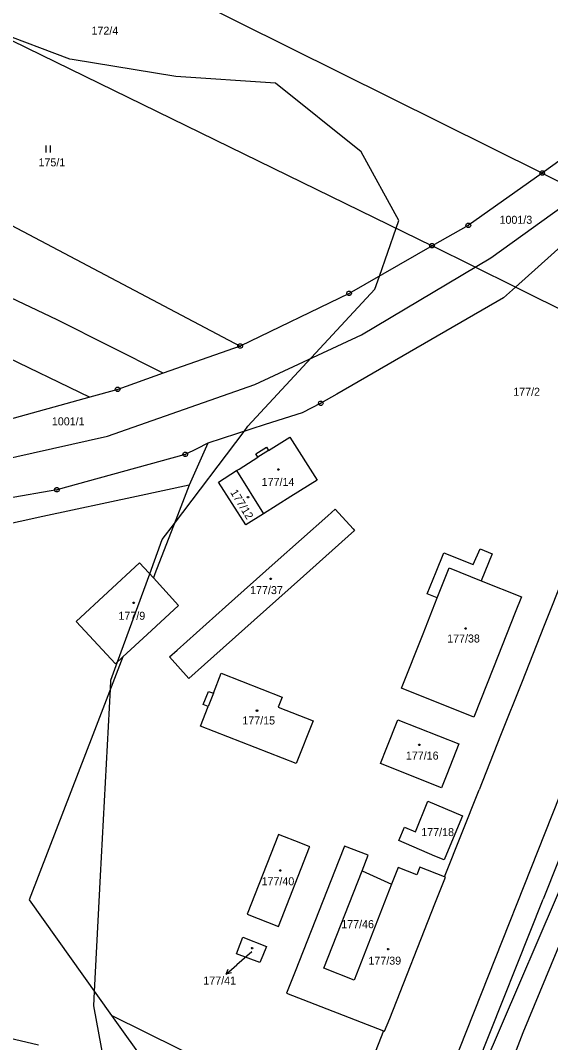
# Model space of a CAD drawing. Extents: x -755359 to -754474, y -1162585 to -1161655.
# Drawn here: x -755011 to -754898.3, y -1162361.4 to -1162144.3 of the extents above; entities that cross this region are included whole.
import ezdxf

# ---------------------------------------------------------------- set-up
doc = ezdxf.new("R2010")
doc.units = 0
for name, color, linetype in [('Vrstva 1', 7, 'Continuous'), ('Vrstva 11', 7, 'Continuous'), ('Vrstva 12', 7, 'Continuous'), ('Vrstva 2', 7, 'Continuous'), ('Vrstva 3', 7, 'Continuous'), ('Vrstva 4', 7, 'Continuous'), ('Vrstva 5', 7, 'Continuous'), ('Vrstva 6', 7, 'Continuous'), ('Vrstva 7', 7, 'Continuous'), ('Vrstva 8', 7, 'Continuous')]:
    doc.layers.add(name, color=color, linetype=linetype)

msp = doc.modelspace()

# ---------------------------------------------------------------- linework, layer by layer
at = {"layer": 'Vrstva 1'}
for p, q in [((-754900.06, -1162176.77), (-755075.64, -1162089.56)), ((-755078.18, -1162116.73), (-754923.5, -1162192.2)), ((-754896.07, -1162173.88), (-754900.06, -1162176.77)), ((-754900.06, -1162176.77), (-754915.78, -1162187.87)), ((-754900.06, -1162176.77), (-754886.23, -1162183.69)), ((-755003.14, -1162207.94), (-755054.32, -1162183.78)), ((-754888.26, -1162185.23), (-754905.78, -1162201)), ((-755012.93, -1162187.79), (-754964.26, -1162213.49)), ((-754915.78, -1162187.87), (-754923.5, -1162192.2)), ((-754923.5, -1162192.2), (-754941.12, -1162202.31)), ((-754905.78, -1162201), (-754923.5, -1162192.2)), ((-754905.78, -1162201), (-754908.27, -1162203.24)), ((-754876.85, -1162215.37), (-754905.78, -1162201)), ((-755040.35, -1162203.08), (-754996.22, -1162224.35)), ((-754941.12, -1162202.31), (-754964.26, -1162213.49)), ((-754908.27, -1162203.24), (-754943.74, -1162223.69)), ((-754980.63, -1162219.28), (-755003.14, -1162207.94)), ((-754964.26, -1162213.49), (-754980.63, -1162219.28)), ((-754980.63, -1162219.28), (-754990.29, -1162222.69)), ((-754990.29, -1162222.69), (-754996.22, -1162224.35)), ((-754996.22, -1162224.35), (-755014.83, -1162229.55)), ((-754943.74, -1162223.69), (-754947.14, -1162225.65)), ((-754947.14, -1162225.65), (-754951.07, -1162227.67)), ((-754951.07, -1162227.67), (-754958.95, -1162230.19)), ((-754958.95, -1162230.19), (-754971.15, -1162234.1)), ((-754958.23, -1162235.71), (-754953.68, -1162232.85)), ((-754953.68, -1162232.85), (-754947.93, -1162241.97)), ((-754973.51, -1162235.29), (-754975.93, -1162236.51)), ((-754972, -1162236.02), (-754975.1, -1162243.04)), ((-754971.15, -1162234.1), (-754973.51, -1162235.29)), ((-754971.15, -1162234.1), (-754972, -1162236.02)), ((-754960.95, -1162236.39), (-754958.69, -1162234.97)), ((-754958.69, -1162234.97), (-754958.23, -1162235.71)), ((-754975.93, -1162236.51), (-754994.22, -1162241.55)), ((-754964.51, -1162239.63), (-754960.48, -1162237.12)), ((-754960.48, -1162237.12), (-754960.95, -1162236.39)), ((-754968.85, -1162242.38), (-754965.02, -1162239.9)), ((-754965.02, -1162239.9), (-754964.51, -1162239.63)), ((-754965.02, -1162239.9), (-754959.28, -1162249.1)), ((-754994.22, -1162241.55), (-755003.23, -1162244.03)), ((-754963.09, -1162251.49), (-754968.85, -1162242.38)), ((-754947.93, -1162241.97), (-754953.52, -1162245.48)), ((-755003.23, -1162244.03), (-755013.79, -1162245.86)), ((-754975.1, -1162243.04), (-754986.3, -1162245.44)), ((-754975.1, -1162243.04), (-754977.59, -1162249.49)), ((-754986.3, -1162245.44), (-755006.22, -1162249.72)), ((-754953.52, -1162245.48), (-754959.28, -1162249.1)), ((-754959.28, -1162249.1), (-754963.09, -1162251.49)), ((-754945.64, -1162249.55), (-754944.05, -1162248.14)), ((-754944.05, -1162248.14), (-754940.25, -1162252.33)), ((-755006.22, -1162249.72), (-755027.5, -1162254.28)), ((-754977.59, -1162249.49), (-754982.38, -1162261.87)), ((-754956.8, -1162259.49), (-754945.64, -1162249.55)), ((-754950.82, -1162262.37), (-754939.94, -1162252.67)), ((-754940.25, -1162252.33), (-754939.94, -1162252.67)), ((-754922.63, -1162261.43), (-754921.01, -1162257.39)), ((-754921.01, -1162257.39), (-754914.72, -1162259.89)), ((-754914.72, -1162259.89), (-754913.29, -1162256.54)), ((-754913.29, -1162256.54), (-754910.69, -1162257.6)), ((-754910.69, -1162257.6), (-754913.05, -1162263.33)), ((-754985.67, -1162259.55), (-754999.09, -1162271.99)), ((-754985.67, -1162259.55), (-754982.72, -1162262.75)), ((-754967.36, -1162268.89), (-754956.8, -1162259.49)), ((-754982.38, -1162261.87), (-754982.72, -1162262.75)), ((-754924.5, -1162266.11), (-754922.63, -1162261.43)), ((-754895.21, -1162261.65), (-754899.8, -1162273.21)), ((-754982.72, -1162262.75), (-754977.34, -1162268.59)), ((-754961.31, -1162271.72), (-754950.82, -1162262.37)), ((-754913.05, -1162263.33), (-754904.47, -1162266.73)), ((-754922.38, -1162266.96), (-754924.5, -1162266.11)), ((-754977.34, -1162268.59), (-754984.03, -1162274.74)), ((-754930.02, -1162407.36), (-754870.17, -1162267.96)), ((-754925.41, -1162274.6), (-754922.38, -1162266.96)), ((-754904.47, -1162266.73), (-754905.81, -1162270.11)), ((-754977.67, -1162278.08), (-754967.36, -1162268.89)), ((-754905.81, -1162270.11), (-754910.45, -1162281.8)), ((-754990.78, -1162280.96), (-754999.09, -1162271.99)), ((-754971.86, -1162281.13), (-754961.31, -1162271.72)), ((-754989.19, -1162279.49), (-754984.03, -1162274.74)), ((-754930, -1162286.19), (-754925.41, -1162274.6)), ((-754899.8, -1162273.21), (-754904.37, -1162284.73)), ((-754989.19, -1162279.49), (-754995.6, -1162296.07)), ((-754989.19, -1162279.49), (-754990.78, -1162280.96)), ((-754979.27, -1162279.5), (-754977.67, -1162278.08)), ((-754979.27, -1162279.5), (-754975.18, -1162284.09)), ((-754975.18, -1162284.09), (-754971.86, -1162281.13)), ((-754969.96, -1162287.23), (-754968.29, -1162283)), ((-754968.29, -1162283), (-754955.36, -1162288.07)), ((-754910.45, -1162281.8), (-754914.62, -1162292.29)), ((-754904.37, -1162284.73), (-754908.92, -1162296.21)), ((-754972.13, -1162289.65), (-754971, -1162286.83)), ((-754971, -1162286.83), (-754969.96, -1162287.23)), ((-754955.36, -1162288.07), (-754956.18, -1162290.17)), ((-754914.62, -1162292.29), (-754930, -1162286.19)), ((-754972.72, -1162294.22), (-754971.08, -1162290.06)), ((-754971.08, -1162290.06), (-754972.13, -1162289.65)), ((-754956.18, -1162290.17), (-754948.75, -1162293.08)), ((-754952.39, -1162302.17), (-754972.72, -1162294.22)), ((-754948.75, -1162293.08), (-754952.39, -1162302.17)), ((-754933.11, -1162298.79), (-754930.78, -1162292.9)), ((-754930.78, -1162292.9), (-754917.8, -1162298.01)), ((-754995.6, -1162296.07), (-755004.94, -1162320.25)), ((-754908.92, -1162296.21), (-754913.49, -1162307.74)), ((-754934.43, -1162302.13), (-754933.11, -1162298.79)), ((-754917.8, -1162298.01), (-754920.35, -1162304.49)), ((-754921.45, -1162307.29), (-754934.43, -1162302.13)), ((-754920.35, -1162304.49), (-754921.45, -1162307.29)), ((-754920.81, -1162326.21), (-754913.49, -1162307.74)), ((-754927.01, -1162316.65), (-754924.39, -1162310.17)), ((-754924.39, -1162310.17), (-754917, -1162313.28)), ((-754917, -1162313.28), (-754919.73, -1162319.74)), ((-754930.54, -1162318.52), (-754929.32, -1162315.68)), ((-754929.32, -1162315.68), (-754927.01, -1162316.65)), ((-754956.15, -1162317.23), (-754962.81, -1162334.17)), ((-754951.35, -1162319.11), (-754956.15, -1162317.23)), ((-754922.89, -1162321.82), (-754930.54, -1162318.52)), ((-755004.94, -1162320.25), (-755009.14, -1162331.11)), ((-754956.1, -1162336.8), (-754949.5, -1162319.95)), ((-754949.46, -1162319.85), (-754951.35, -1162319.11)), ((-754949.5, -1162319.95), (-754949.46, -1162319.85)), ((-754942.11, -1162319.68), (-754943.32, -1162322.74)), ((-754937.04, -1162321.65), (-754942.11, -1162319.68)), ((-754919.73, -1162319.74), (-754920.94, -1162322.61)), ((-754887.61, -1162319.28), (-754904.19, -1162359.38)), ((-754943.32, -1162322.74), (-754952.59, -1162346.32)), ((-754938.35, -1162324.98), (-754937.04, -1162321.65)), ((-754920.94, -1162322.61), (-754922.89, -1162321.82)), ((-754946.47, -1162345.65), (-754938.35, -1162324.98)), ((-754938.35, -1162324.98), (-754932.08, -1162327.81)), ((-754930.68, -1162324.22), (-754932.08, -1162327.81)), ((-754926.7, -1162325.77), (-754930.68, -1162324.22)), ((-754926.07, -1162324.16), (-754926.7, -1162325.77)), ((-754920.81, -1162326.21), (-754926.07, -1162324.16)), ((-754922.89, -1162331.96), (-754920.65, -1162326.27)), ((-754920.65, -1162326.27), (-754920.81, -1162326.21)), ((-754932.08, -1162327.81), (-754940.04, -1162348.18)), ((-755009.14, -1162331.11), (-754991.59, -1162355.66)), ((-754932.49, -1162356.33), (-754922.89, -1162331.96)), ((-754962.81, -1162334.17), (-754956.1, -1162336.8)), ((-754964.25, -1162340.51), (-754963.68, -1162339.01)), ((-754963.68, -1162339.01), (-754958.7, -1162341)), ((-755096.49, -1162341), (-755007.12, -1162361.91)), ((-754965.03, -1162342.55), (-754964.25, -1162340.51)), ((-754960.08, -1162344.45), (-754965.03, -1162342.55)), ((-754958.7, -1162341), (-754959.46, -1162342.9)), ((-754959.46, -1162342.9), (-754960.08, -1162344.45)), ((-754952.59, -1162346.32), (-754954.4, -1162350.9)), ((-754940.04, -1162348.18), (-754946.47, -1162345.65)), ((-754954.4, -1162350.9), (-754933.79, -1162358.94)), ((-754942.18, -1162380.1), (-754991.59, -1162355.66)), ((-754991.59, -1162355.66), (-754983.11, -1162367.53)), ((-754933.56, -1162359.03), (-754932.49, -1162356.33)), ((-754933.79, -1162358.94), (-754942.18, -1162380.1)), ((-754933.79, -1162358.94), (-754933.56, -1162359.03)), ((-754904.19, -1162359.38), (-754920.39, -1162401.05))]:
    msp.add_line(p, q, dxfattribs=at)
at = {"layer": 'Vrstva 11'}
for p, q in [((-755000.49, -1162152.59), (-755019.15, -1162145.53)), ((-755000, -1162152.67), (-755000.49, -1162152.59)), ((-754977.91, -1162156.23), (-755000, -1162152.67)), ((-754956.78, -1162157.69), (-754977.91, -1162156.23)), ((-754938.57, -1162172.26), (-754956.78, -1162157.69)), ((-754930.56, -1162186.83), (-754938.57, -1162172.26)), ((-754931.13, -1162188.48), (-754930.56, -1162186.83)), ((-754934.68, -1162198.62), (-754931.13, -1162188.48)), ((-754935.66, -1162201.4), (-754934.68, -1162198.62)), ((-754962.61, -1162230.54), (-754935.66, -1162201.4)), ((-754978.24, -1162251.17), (-754963.43, -1162231.63)), ((-754963.43, -1162231.63), (-754962.61, -1162230.54)), ((-754980.82, -1162254.58), (-754978.24, -1162251.17)), ((-754983.5, -1162261.9), (-754980.82, -1162254.58)), ((-754990.32, -1162280.53), (-754983.5, -1162261.9)), ((-754991.75, -1162284.45), (-754990.32, -1162280.53)), ((-754991.85, -1162286.38), (-754991.75, -1162284.45)), ((-754993.94, -1162325.98), (-754991.85, -1162286.38)), ((-754887.61, -1162319.28), (-754904.19, -1162359.38)), ((-754995.23, -1162350.57), (-754993.94, -1162325.98)), ((-754995.39, -1162353.66), (-754995.23, -1162350.57)), ((-754993.26, -1162365.15), (-754995.39, -1162353.66)), ((-754904.19, -1162359.38), (-754920.39, -1162401.05))]:
    msp.add_line(p, q, dxfattribs=at)
at = {"layer": 'Vrstva 12'}
for p, q in [((-754958.23, -1162235.71), (-754953.68, -1162232.85)), ((-754953.68, -1162232.85), (-754947.93, -1162241.97)), ((-754958.23, -1162235.71), (-754960.48, -1162237.12)), ((-754964.51, -1162239.63), (-754960.48, -1162237.12)), ((-754968.85, -1162242.38), (-754965.02, -1162239.9)), ((-754965.02, -1162239.9), (-754964.51, -1162239.63)), ((-754965.02, -1162239.9), (-754959.28, -1162249.1)), ((-754965.02, -1162239.9), (-754959.28, -1162249.1)), ((-754963.09, -1162251.49), (-754968.85, -1162242.38)), ((-754947.93, -1162241.97), (-754953.52, -1162245.48)), ((-754953.52, -1162245.48), (-754959.28, -1162249.1)), ((-754959.28, -1162249.1), (-754963.09, -1162251.49)), ((-754945.64, -1162249.55), (-754944.05, -1162248.14)), ((-754944.05, -1162248.14), (-754940.25, -1162252.33)), ((-754956.8, -1162259.49), (-754945.64, -1162249.55)), ((-754950.82, -1162262.37), (-754939.94, -1162252.67)), ((-754940.25, -1162252.33), (-754939.94, -1162252.67)), ((-754985.67, -1162259.55), (-754999.09, -1162271.99)), ((-754985.67, -1162259.55), (-754982.72, -1162262.75)), ((-754967.36, -1162268.89), (-754956.8, -1162259.49)), ((-754922.38, -1162266.96), (-754919.87, -1162260.62)), ((-754919.87, -1162260.62), (-754913.05, -1162263.33)), ((-754982.72, -1162262.75), (-754977.34, -1162268.59)), ((-754961.31, -1162271.72), (-754950.82, -1162262.37)), ((-754913.05, -1162263.33), (-754904.47, -1162266.73)), ((-754977.34, -1162268.59), (-754984.03, -1162274.74)), ((-754925.41, -1162274.6), (-754922.38, -1162266.96)), ((-754904.47, -1162266.73), (-754905.81, -1162270.11)), ((-754977.67, -1162278.08), (-754967.36, -1162268.89)), ((-754905.81, -1162270.11), (-754910.45, -1162281.8)), ((-754990.78, -1162280.96), (-754999.09, -1162271.99)), ((-754971.86, -1162281.13), (-754961.31, -1162271.72)), ((-754989.19, -1162279.49), (-754984.03, -1162274.74)), ((-754930, -1162286.19), (-754925.41, -1162274.6)), ((-754989.19, -1162279.49), (-754990.78, -1162280.96)), ((-754979.27, -1162279.5), (-754977.67, -1162278.08)), ((-754979.27, -1162279.5), (-754975.18, -1162284.09)), ((-754975.18, -1162284.09), (-754971.86, -1162281.13)), ((-754969.96, -1162287.23), (-754968.29, -1162283)), ((-754968.29, -1162283), (-754955.36, -1162288.07)), ((-754910.45, -1162281.8), (-754914.62, -1162292.29)), ((-754969.96, -1162287.23), (-754971.08, -1162290.06)), ((-754955.36, -1162288.07), (-754956.18, -1162290.17)), ((-754914.62, -1162292.29), (-754930, -1162286.19)), ((-754972.72, -1162294.22), (-754971.08, -1162290.06)), ((-754956.18, -1162290.17), (-754948.75, -1162293.08)), ((-754952.39, -1162302.17), (-754972.72, -1162294.22)), ((-754948.75, -1162293.08), (-754952.39, -1162302.17)), ((-754933.11, -1162298.79), (-754930.78, -1162292.9)), ((-754930.78, -1162292.9), (-754917.8, -1162298.01)), ((-754934.43, -1162302.13), (-754933.11, -1162298.79)), ((-754917.8, -1162298.01), (-754920.35, -1162304.49)), ((-754921.45, -1162307.29), (-754934.43, -1162302.13)), ((-754920.35, -1162304.49), (-754921.45, -1162307.29)), ((-754956.15, -1162317.23), (-754962.81, -1162334.17)), ((-754951.35, -1162319.11), (-754956.15, -1162317.23)), ((-754956.1, -1162336.8), (-754949.5, -1162319.95)), ((-754949.46, -1162319.85), (-754951.35, -1162319.11)), ((-754949.5, -1162319.95), (-754949.46, -1162319.85)), ((-754942.11, -1162319.68), (-754943.32, -1162322.74)), ((-754937.04, -1162321.65), (-754942.11, -1162319.68)), ((-754943.32, -1162322.74), (-754952.59, -1162346.32)), ((-754938.35, -1162324.98), (-754937.04, -1162321.65)), ((-754946.47, -1162345.65), (-754938.35, -1162324.98)), ((-754930.68, -1162324.22), (-754932.08, -1162327.81)), ((-754926.7, -1162325.77), (-754930.68, -1162324.22)), ((-754926.07, -1162324.16), (-754926.7, -1162325.77)), ((-754920.81, -1162326.21), (-754926.07, -1162324.16)), ((-754922.89, -1162331.96), (-754920.65, -1162326.27)), ((-754920.65, -1162326.27), (-754920.81, -1162326.21)), ((-754932.08, -1162327.81), (-754940.04, -1162348.18)), ((-754932.49, -1162356.33), (-754922.89, -1162331.96)), ((-754962.81, -1162334.17), (-754956.1, -1162336.8)), ((-754964.25, -1162340.51), (-754963.68, -1162339.01)), ((-754963.68, -1162339.01), (-754958.7, -1162341)), ((-754965.03, -1162342.55), (-754964.25, -1162340.51)), ((-754960.08, -1162344.45), (-754965.03, -1162342.55)), ((-754958.7, -1162341), (-754959.46, -1162342.9)), ((-754959.46, -1162342.9), (-754960.08, -1162344.45)), ((-754952.59, -1162346.32), (-754954.4, -1162350.9)), ((-754940.04, -1162348.18), (-754946.47, -1162345.65)), ((-754954.4, -1162350.9), (-754933.79, -1162358.94)), ((-754933.56, -1162359.03), (-754932.49, -1162356.33)), ((-754933.79, -1162358.94), (-754933.56, -1162359.03))]:
    msp.add_line(p, q, dxfattribs=at)
at = {"layer": 'Vrstva 3'}
for p, q in [((-755005.55, -1162170.88), (-755005.55, -1162172.38)), ((-755004.55, -1162172.38), (-755004.55, -1162170.88))]:
    msp.add_line(p, q, dxfattribs=at)
at = {"layer": 'Vrstva 4'}
for p, q in [((-754958.23, -1162235.71), (-754960.48, -1162237.12)), ((-754922.38, -1162266.96), (-754919.87, -1162260.62)), ((-754919.87, -1162260.62), (-754913.05, -1162263.33)), ((-754969.96, -1162287.23), (-754971.08, -1162290.06))]:
    msp.add_line(p, q, dxfattribs=at)
at = {"layer": 'Vrstva 5'}
for points in [[(-754956.04, -1162239.57), (-754955.95, -1162239.72), (-754956.04, -1162239.87), (-754956.22, -1162239.87), (-754956.31, -1162239.72), (-754956.22, -1162239.57)], [(-754962.5, -1162245.43), (-754962.41, -1162245.58), (-754962.5, -1162245.73), (-754962.68, -1162245.73), (-754962.77, -1162245.58), (-754962.68, -1162245.43)], [(-754957.71, -1162262.76), (-754957.62, -1162262.91), (-754957.71, -1162263.06), (-754957.89, -1162263.06), (-754957.98, -1162262.91), (-754957.89, -1162262.76)], [(-754986.8, -1162267.87), (-754986.71, -1162268.02), (-754986.8, -1162268.17), (-754986.98, -1162268.17), (-754987.07, -1162268.02), (-754986.98, -1162267.87)], [(-754916.28, -1162273.31), (-754916.19, -1162273.46), (-754916.28, -1162273.61), (-754916.46, -1162273.61), (-754916.55, -1162273.46), (-754916.46, -1162273.31)], [(-754960.61, -1162290.79), (-754960.52, -1162290.94), (-754960.61, -1162291.09), (-754960.79, -1162291.09), (-754960.88, -1162290.94), (-754960.79, -1162290.79)], [(-754926.11, -1162298.05), (-754926.02, -1162298.2), (-754926.11, -1162298.35), (-754926.29, -1162298.35), (-754926.38, -1162298.2), (-754926.29, -1162298.05)], [(-754955.67, -1162324.74), (-754955.58, -1162324.89), (-754955.67, -1162325.04), (-754955.85, -1162325.04), (-754955.94, -1162324.89), (-754955.85, -1162324.74)], [(-754961.64, -1162341.23), (-754961.55, -1162341.38), (-754961.64, -1162341.53), (-754961.82, -1162341.53), (-754961.91, -1162341.38), (-754961.82, -1162341.23)], [(-754932.73, -1162341.43), (-754932.64, -1162341.58), (-754932.73, -1162341.73), (-754932.91, -1162341.73), (-754933, -1162341.58), (-754932.91, -1162341.43)]]:
    msp.add_lwpolyline(points, close=True, dxfattribs=at)
at = {"layer": 'Vrstva 6'}
for p, q in [((-755000.46, -1162571.42), (-754786.74, -1162032.64)), ((-754910.99, -1162194.73), (-754890.36, -1162179.87)), ((-754938.51, -1162211.08), (-754910.99, -1162194.73)), ((-754961.14, -1162221.64), (-754938.51, -1162211.08)), ((-754992.46, -1162232.61), (-754961.14, -1162221.64)), ((-755031.48, -1162241.38), (-754992.46, -1162232.61)), ((-754878.79, -1162277.91), (-754899.91, -1162330.95)), ((-754934.61, -1162418.42), (-754899.91, -1162330.95))]:
    msp.add_line(p, q, dxfattribs=at)
at = {"layer": 'Vrstva 7'}
for p in [(-754961.81, -1162342.17), (-754967.215, -1162346.909)]:
    msp.add_line(p, (-754964.96, -1162344.93), dxfattribs=at)
msp.add_lwpolyline([(-754966.134, -1162346.625), (-754967.215, -1162346.909), (-754966.793, -1162345.873)], dxfattribs=at)
at = {"layer": 'Vrstva 8'}
for p, q in [((-754900.18, -1162176.77), (-754899.94, -1162176.77)), ((-754915.9, -1162187.87), (-754915.66, -1162187.87)), ((-754923.62, -1162192.2), (-754923.38, -1162192.2)), ((-754941.24, -1162202.31), (-754941, -1162202.31)), ((-754964.38, -1162213.49), (-754964.14, -1162213.49)), ((-754990.41, -1162222.69), (-754990.17, -1162222.69)), ((-754947.26, -1162225.65), (-754947.02, -1162225.65)), ((-754976.05, -1162236.51), (-754975.81, -1162236.51)), ((-755003.35, -1162244.03), (-755003.11, -1162244.03))]:
    msp.add_line(p, q, dxfattribs=at)
for points in [[(-754899.91, -1162176.29), (-754899.66, -1162176.47), (-754899.56, -1162176.76), (-754899.66, -1162177.05), (-754899.91, -1162177.23), (-754900.22, -1162177.23), (-754900.47, -1162177.05), (-754900.57, -1162176.76), (-754900.47, -1162176.47), (-754900.22, -1162176.29)], [(-754915.63, -1162187.39), (-754915.38, -1162187.57), (-754915.28, -1162187.86), (-754915.38, -1162188.15), (-754915.63, -1162188.33), (-754915.94, -1162188.33), (-754916.19, -1162188.15), (-754916.29, -1162187.86), (-754916.19, -1162187.57), (-754915.94, -1162187.39)], [(-754923.35, -1162191.72), (-754923.1, -1162191.9), (-754923, -1162192.19), (-754923.1, -1162192.48), (-754923.35, -1162192.66), (-754923.66, -1162192.66), (-754923.91, -1162192.48), (-754924.01, -1162192.19), (-754923.91, -1162191.9), (-754923.66, -1162191.72)], [(-754940.97, -1162201.83), (-754940.72, -1162202.01), (-754940.62, -1162202.3), (-754940.72, -1162202.59), (-754940.97, -1162202.77), (-754941.28, -1162202.77), (-754941.53, -1162202.59), (-754941.63, -1162202.3), (-754941.53, -1162202.01), (-754941.28, -1162201.83)], [(-754964.11, -1162213.01), (-754963.86, -1162213.19), (-754963.76, -1162213.48), (-754963.86, -1162213.77), (-754964.11, -1162213.95), (-754964.42, -1162213.95), (-754964.67, -1162213.77), (-754964.77, -1162213.48), (-754964.67, -1162213.19), (-754964.42, -1162213.01)], [(-754990.14, -1162222.21), (-754989.89, -1162222.39), (-754989.79, -1162222.68), (-754989.89, -1162222.97), (-754990.14, -1162223.15), (-754990.45, -1162223.15), (-754990.7, -1162222.97), (-754990.8, -1162222.68), (-754990.7, -1162222.39), (-754990.45, -1162222.21)], [(-754946.99, -1162225.17), (-754946.74, -1162225.35), (-754946.64, -1162225.64), (-754946.74, -1162225.93), (-754946.99, -1162226.11), (-754947.3, -1162226.11), (-754947.55, -1162225.93), (-754947.65, -1162225.64), (-754947.55, -1162225.35), (-754947.3, -1162225.17)], [(-754975.78, -1162236.03), (-754975.53, -1162236.21), (-754975.43, -1162236.5), (-754975.53, -1162236.79), (-754975.78, -1162236.97), (-754976.09, -1162236.97), (-754976.34, -1162236.79), (-754976.44, -1162236.5), (-754976.34, -1162236.21), (-754976.09, -1162236.03)], [(-755003.08, -1162243.55), (-755002.83, -1162243.73), (-755002.73, -1162244.02), (-755002.83, -1162244.31), (-755003.08, -1162244.49), (-755003.39, -1162244.49), (-755003.64, -1162244.31), (-755003.74, -1162244.02), (-755003.64, -1162243.73), (-755003.39, -1162243.55)]]:
    msp.add_lwpolyline(points, close=True, dxfattribs=at)

# ---------------------------------------------------------------- texts
at = {"layer": 'Vrstva 2'}
for s, height, p in [('172/4', 1.7, (-754995.867, -1162147.36)), ('175/1', 1.7, (-755007.127, -1162175.33)), ('1001/3', 1.7, (-754909.147, -1162187.53)), ('177/2', 1.7, (-754906.237, -1162224.05)), ('1001/1', 1.7, (-755004.287, -1162230.34)), ('177/14', 1.7, (-754959.697, -1162243.21)), ('177/37', 1.7, (-754962.151, -1162266.18)), ('177/9', 1.7, (-754990.135, -1162271.63)), ('177/38', 1.7, (-754920.281, -1162276.46)), ('177/15', 1.7, (-754963.807, -1162293.87)), ('177/16', 1.7, (-754929.057, -1162301.33)), ('177/18', 1.7, (-754925.776, -1162317.57)), ('177/40', 1.7, (-754959.721, -1162328.02)), ('177/46', 1.7, (-754942.784, -1162337.13)), ('177/41', 0.1, (-754962.007, -1162342.17)), ('177/39', 1.7, (-754937.011, -1162344.88))]:
    msp.add_text(s, height=height, dxfattribs=at).set_placement(p)
msp.add_text('177/12', height=1.7, rotation=301.49039, dxfattribs=at).set_placement((-754966.435, -1162244.575))
at = {"layer": 'Vrstva 7'}
msp.add_text('177/41', height=1.7, dxfattribs=at).set_placement((-754972.096, -1162349.1))

doc.saveas('drawing.dxf')
